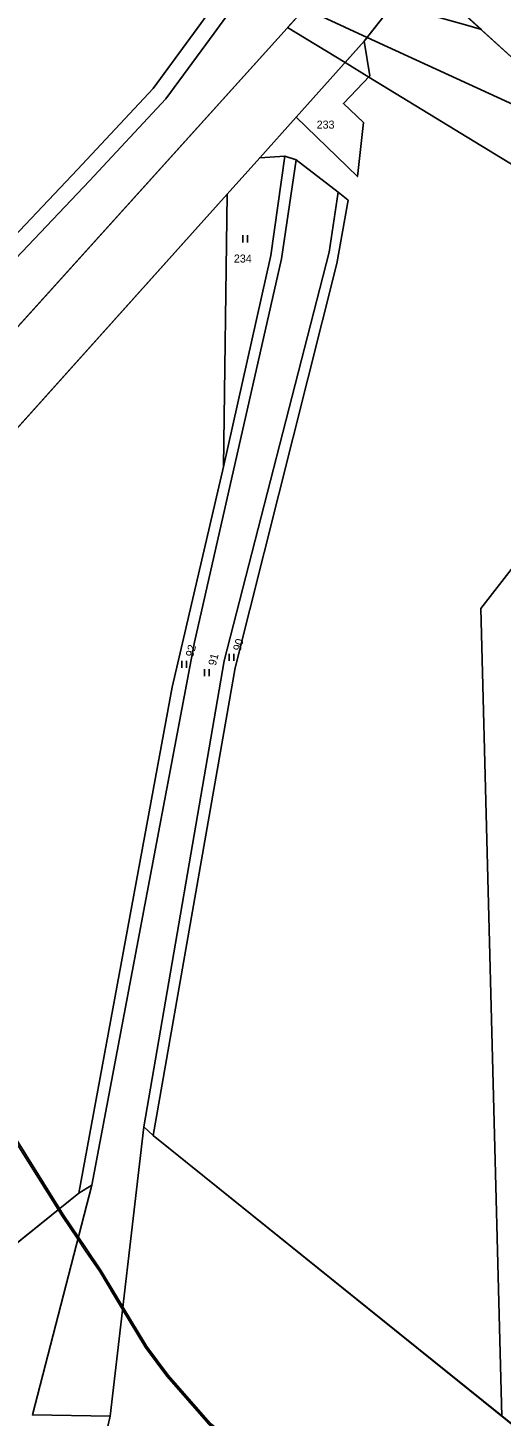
# Model space of a CAD drawing. Extents: x -689422 to -685210, y -987725 to -982160.
# Drawn here: x -685954.8 to -685854.1, y -987007.8 to -986712.9 of the extents above; entities that cross this region are included whole.
import ezdxf

# ---------------------------------------------------------------- set-up
doc = ezdxf.new("R2010")
doc.units = 0
for name, color, linetype in [('KN_Hranice_parcel', 7, 'Continuous'), ('KN_Parcelni cisla', 7, 'Continuous'), ('KN_Polygon parcely', 7, 'Continuous'), ('KN_POZEMKY_ORNA PUDA', 7, 'Continuous'), ('KN_POZEMKY_OSTATNI PLOCHA', 7, 'Continuous'), ('KN_POZEMKY_TTP', 7, 'Continuous'), ('KN_VYUZITI_16_ostatni plocha_silnice', 7, 'Continuous'), ('KN_VYUZITI_17_ostatni plocha_ostatni komunikace', 7, 'Continuous'), ('KN_VYUZITI_23_ostatni plocha_manipulacni plocha', 7, 'Continuous'), ('KN_Věcná břemena k části', 7, 'Continuous'), ('KN_Značky kultur', 7, 'Continuous')]:
    doc.layers.add(name, color=color, linetype=linetype)

msp = doc.modelspace()

# ---------------------------------------------------------------- linework, layer by layer
at = {"layer": 'KN_Hranice_parcel'}
for p, q in [((-685871.78, -986701.06), (-685883.26, -986715.76)), ((-685848.24, -986722.49), (-685871.78, -986701.06)), ((-685896.42, -986709.33), (-686030, -986857.27)), ((-685897.76, -986731.9), (-685883.26, -986715.76)), ((-685897.76, -986731.9), (-685905.48, -986740.5)), ((-685905.48, -986740.5), (-685900.17, -986740.16)), ((-685900.17, -986740.16), (-685897.77, -986740.94)), ((-685912.44, -986748.24), (-685905.48, -986740.5)), ((-685897.77, -986740.94), (-685888.84, -986747.84)), ((-685912.44, -986748.24), (-686007.7, -986854.28)), ((-685913.21, -986806.14), (-685912.44, -986748.24)), ((-685930.15, -986946.38), (-685937.3, -987007.82)), ((-685928.15, -986948.17), (-685930.15, -986946.38)), ((-685841.86, -987017.57), (-685928.15, -986948.17)), ((-685943.98, -986960.44), (-686030.41, -987030.08)), ((-685953.84, -987007.56), (-685941.2, -986958.77)), ((-685941.2, -986958.77), (-685943.98, -986960.44)), ((-685937.3, -987007.82), (-685953.84, -987007.56))]:
    msp.add_line(p, q, dxfattribs=at)
for points in [[(-685883.26, -986715.76), (-685882.04, -986723.11), (-685887.69, -986728.97), (-685883.44, -986733.01), (-685884.73, -986744.52), (-685897.76, -986731.9)], [(-685900.17, -986740.16), (-685903.1, -986761.27), (-685913.21, -986806.14)], [(-685897.77, -986740.94), (-685900.89, -986761.99), (-685919.33, -986843.38), (-685941.2, -986958.77)], [(-685888.84, -986747.84), (-685890.73, -986760.55), (-685913.08, -986847.4), (-685930.15, -986946.38)], [(-685888.84, -986747.84), (-685886.69, -986749.54), (-685889.1, -986762.96), (-685910.74, -986848.85), (-685928.15, -986948.17)], [(-685943.98, -986960.44), (-685924.13, -986852.94), (-685913.21, -986806.14)], [(-685937.3, -987007.82), (-685938.29, -987012.04), (-685944.18, -987021.29), (-685944.36, -987022.19)]]:
    msp.add_lwpolyline(points, dxfattribs=at)
at = {"layer": 'KN_Polygon parcely'}
for points in [[(-686030, -986857.27), (-685896.42, -986709.33), (-685879.25, -986604.88), (-685888.64, -986596.36), (-685893.37, -986592.13), (-685934.98, -986554.78), (-685848.74, -986459.34), (-685824.6, -986333.83), (-685808.02, -986261.49), (-685804.53, -986262.81), (-685805.53, -986255.07), (-685812.11, -986245.12), (-685839.77, -986231.67)], [(-686007.7, -986854.28), (-685912.44, -986748.24), (-685905.48, -986740.5), (-685897.76, -986731.9), (-685883.26, -986715.76), (-685871.78, -986701.06), (-685873.39, -986699.91), (-685878.76, -986694.71), (-685879.32, -986694.17), (-685881.14, -986692.41), (-685892.53, -986705.03), (-685896.42, -986709.33), (-686030, -986857.27)], [(-685871.78, -986701.06), (-685848.24, -986722.49), (-685839.62, -986712.96), (-685835.01, -986707.92)], [(-685841.86, -987017.57), (-685928.15, -986948.17), (-685930.15, -986946.38), (-685937.3, -987007.82), (-685938.29, -987012.04)]]:
    msp.add_lwpolyline(points, dxfattribs=at)
for points in [[(-685848.24, -986722.49), (-685871.78, -986701.06), (-685883.26, -986715.76), (-685882.04, -986723.11), (-685887.69, -986728.97), (-685883.44, -986733.01), (-685884.73, -986744.52), (-685897.76, -986731.9), (-685905.48, -986740.5), (-685900.17, -986740.16), (-685897.77, -986740.94), (-685888.84, -986747.84), (-685886.69, -986749.54), (-685889.1, -986762.96), (-685910.74, -986848.85), (-685928.15, -986948.17), (-685841.86, -987017.57), (-685785.3, -986953.97), (-685700.06, -986858.13), (-685729.36, -986831.55), (-685790.39, -986775.56)], [(-685883.26, -986715.76), (-685897.76, -986731.9), (-685884.73, -986744.52), (-685883.44, -986733.01), (-685887.69, -986728.97), (-685882.04, -986723.11)], [(-685913.21, -986806.14), (-685924.13, -986852.94), (-685943.98, -986960.44), (-685941.2, -986958.77), (-685919.33, -986843.38), (-685900.89, -986761.99), (-685897.77, -986740.94), (-685900.17, -986740.16), (-685903.1, -986761.27)], [(-685900.17, -986740.16), (-685905.48, -986740.5), (-685912.44, -986748.24), (-685913.21, -986806.14), (-685903.1, -986761.27)], [(-685919.33, -986843.38), (-685941.2, -986958.77), (-685953.84, -987007.56), (-685937.3, -987007.82), (-685930.15, -986946.38), (-685913.08, -986847.4), (-685890.73, -986760.55), (-685888.84, -986747.84), (-685897.77, -986740.94), (-685900.89, -986761.99)], [(-686057.95, -987027.77), (-686044.81, -987042.84), (-686030.41, -987030.08), (-685943.98, -986960.44), (-685924.13, -986852.94), (-685913.21, -986806.14), (-685912.44, -986748.24), (-686007.7, -986854.28), (-685997.69, -986881.99), (-685975.19, -986944.25), (-685978.21, -986945.31), (-686044.53, -986968.62), (-686066.56, -986976.83), (-686064.65, -986989.12), (-686058.05, -987027.25)], [(-685890.73, -986760.55), (-685913.08, -986847.4), (-685930.15, -986946.38), (-685928.15, -986948.17), (-685910.74, -986848.85), (-685889.1, -986762.96), (-685886.69, -986749.54), (-685888.84, -986747.84)], [(-686016.2, -987083.11), (-686028.95, -987043.29), (-685988.6, -987031.04), (-685980.6, -987028.61), (-685982.92, -987021.97), (-685962.77, -987015.13), (-685959.63, -987023.64), (-685951.53, -987020.94), (-685949.91, -987021.19), (-685944.36, -987022.19), (-685944.18, -987021.29), (-685938.29, -987012.04), (-685937.3, -987007.82), (-685953.84, -987007.56), (-685941.2, -986958.77), (-685943.98, -986960.44), (-686030.41, -987030.08), (-686044.81, -987042.84), (-686051.22, -987045.66), (-686050.62, -987047.03), (-686049.49, -987051.75), (-686046.44, -987058.66), (-686042.51, -987067.97), (-686047.8, -987093.66)]]:
    msp.add_lwpolyline(points, close=True, dxfattribs=at)
at = {"layer": 'KN_POZEMKY_ORNA PUDA'}
for p, q in [((-685883.26, -986715.76), (-685871.78, -986701.06)), ((-685871.78, -986701.06), (-685848.24, -986722.49)), ((-685896.42, -986709.33), (-686030, -986857.27)), ((-685882.04, -986723.11), (-685883.26, -986715.76)), ((-685887.69, -986728.97), (-685882.04, -986723.11)), ((-685883.44, -986733.01), (-685887.69, -986728.97)), ((-685905.48, -986740.5), (-685897.76, -986731.9)), ((-685897.76, -986731.9), (-685884.73, -986744.52)), ((-685884.73, -986744.52), (-685883.44, -986733.01)), ((-685900.17, -986740.16), (-685905.48, -986740.5)), ((-685897.77, -986740.94), (-685900.17, -986740.16)), ((-685888.84, -986747.84), (-685897.77, -986740.94)), ((-686007.7, -986854.28), (-685912.44, -986748.24)), ((-685912.44, -986748.24), (-685913.21, -986806.14)), ((-685886.69, -986749.54), (-685888.84, -986747.84)), ((-685889.1, -986762.96), (-685886.69, -986749.54)), ((-685910.74, -986848.85), (-685889.1, -986762.96)), ((-685913.21, -986806.14), (-685924.13, -986852.94)), ((-685928.15, -986948.17), (-685910.74, -986848.85)), ((-685924.13, -986852.94), (-685943.98, -986960.44)), ((-685841.86, -987017.57), (-685928.15, -986948.17)), ((-685943.98, -986960.44), (-686030.41, -987030.08))]:
    msp.add_line(p, q, dxfattribs=at)
at = {"layer": 'KN_POZEMKY_OSTATNI PLOCHA'}
for p, q in [((-685871.78, -986701.06), (-685883.26, -986715.76)), ((-685848.24, -986722.49), (-685871.78, -986701.06)), ((-686030, -986857.27), (-685896.42, -986709.33)), ((-685883.26, -986715.76), (-685897.76, -986731.9)), ((-685897.76, -986731.9), (-685883.26, -986715.76)), ((-685883.26, -986715.76), (-685882.04, -986723.11)), ((-685882.04, -986723.11), (-685887.69, -986728.97)), ((-685887.69, -986728.97), (-685883.44, -986733.01)), ((-685897.76, -986731.9), (-685905.48, -986740.5)), ((-685884.73, -986744.52), (-685897.76, -986731.9)), ((-685883.44, -986733.01), (-685884.73, -986744.52)), ((-685905.48, -986740.5), (-685912.44, -986748.24)), ((-685912.44, -986748.24), (-686007.7, -986854.28)), ((-686030.41, -987030.08), (-685943.98, -986960.44)), ((-685941.2, -986958.77), (-685953.84, -987007.56)), ((-685943.98, -986960.44), (-685941.2, -986958.77)), ((-685953.84, -987007.56), (-685937.3, -987007.82)), ((-685937.3, -987007.82), (-685938.29, -987012.04))]:
    msp.add_line(p, q, dxfattribs=at)
at = {"layer": 'KN_POZEMKY_TTP'}
for p, q in [((-685905.48, -986740.5), (-685900.17, -986740.16)), ((-685900.17, -986740.16), (-685903.1, -986761.27)), ((-685903.1, -986761.27), (-685900.17, -986740.16)), ((-685900.17, -986740.16), (-685897.77, -986740.94)), ((-685912.44, -986748.24), (-685905.48, -986740.5)), ((-685900.89, -986761.99), (-685897.77, -986740.94)), ((-685897.77, -986740.94), (-685900.89, -986761.99)), ((-685897.77, -986740.94), (-685888.84, -986747.84)), ((-685913.21, -986806.14), (-685912.44, -986748.24)), ((-685888.84, -986747.84), (-685890.73, -986760.55)), ((-685890.73, -986760.55), (-685888.84, -986747.84)), ((-685888.84, -986747.84), (-685886.69, -986749.54)), ((-685886.69, -986749.54), (-685889.1, -986762.96)), ((-685890.73, -986760.55), (-685913.08, -986847.4)), ((-685913.08, -986847.4), (-685890.73, -986760.55)), ((-685919.33, -986843.38), (-685900.89, -986761.99)), ((-685900.89, -986761.99), (-685919.33, -986843.38)), ((-685903.1, -986761.27), (-685913.21, -986806.14)), ((-685913.21, -986806.14), (-685903.1, -986761.27)), ((-685889.1, -986762.96), (-685910.74, -986848.85)), ((-685924.13, -986852.94), (-685913.21, -986806.14)), ((-685941.2, -986958.77), (-685919.33, -986843.38)), ((-685919.33, -986843.38), (-685941.2, -986958.77)), ((-685913.08, -986847.4), (-685930.15, -986946.38)), ((-685930.15, -986946.38), (-685913.08, -986847.4)), ((-685910.74, -986848.85), (-685928.15, -986948.17)), ((-685943.98, -986960.44), (-685924.13, -986852.94)), ((-685937.3, -987007.82), (-685930.15, -986946.38)), ((-685930.15, -986946.38), (-685937.3, -987007.82)), ((-685930.15, -986946.38), (-685928.15, -986948.17)), ((-685928.15, -986948.17), (-685930.15, -986946.38)), ((-685928.15, -986948.17), (-685841.86, -987017.57)), ((-685953.84, -987007.56), (-685941.2, -986958.77)), ((-685941.2, -986958.77), (-685943.98, -986960.44)), ((-685937.3, -987007.82), (-685953.84, -987007.56)), ((-685938.29, -987012.04), (-685937.3, -987007.82))]:
    msp.add_line(p, q, dxfattribs=at)
at = {"layer": 'KN_VYUZITI_16_ostatni plocha_silnice'}
for p, q in [((-685871.78, -986701.06), (-685883.26, -986715.76)), ((-686030, -986857.27), (-685896.42, -986709.33)), ((-685883.26, -986715.76), (-685897.76, -986731.9)), ((-685897.76, -986731.9), (-685905.48, -986740.5)), ((-685905.48, -986740.5), (-685912.44, -986748.24)), ((-685912.44, -986748.24), (-686007.7, -986854.28))]:
    msp.add_line(p, q, dxfattribs=at)
at = {"layer": 'KN_VYUZITI_17_ostatni plocha_ostatni komunikace'}
for p, q in [((-685897.76, -986731.9), (-685883.26, -986715.76)), ((-685883.26, -986715.76), (-685882.04, -986723.11)), ((-685882.04, -986723.11), (-685887.69, -986728.97)), ((-685887.69, -986728.97), (-685883.44, -986733.01)), ((-685884.73, -986744.52), (-685897.76, -986731.9)), ((-685883.44, -986733.01), (-685884.73, -986744.52))]:
    msp.add_line(p, q, dxfattribs=at)
at = {"layer": 'KN_VYUZITI_23_ostatni plocha_manipulacni plocha'}
for p, q in [((-685848.24, -986722.49), (-685871.78, -986701.06)), ((-686030.41, -987030.08), (-685943.98, -986960.44)), ((-685941.2, -986958.77), (-685953.84, -987007.56)), ((-685943.98, -986960.44), (-685941.2, -986958.77)), ((-685953.84, -987007.56), (-685937.3, -987007.82)), ((-685937.3, -987007.82), (-685938.29, -987012.04))]:
    msp.add_line(p, q, dxfattribs=at)
at = {"layer": 'KN_Věcná břemena k části'}
for points in [[(-686029.97, -986842.1), (-686030.24, -986841.61), (-686018.66, -986828.44), (-686002.29, -986809.43), (-685978.75, -986785.37), (-685963.92, -986768.8), (-685941.71, -986745.38), (-685925.43, -986728.01), (-685915.2, -986714.04), (-685896.7, -986688.59), (-685890.74, -986683.93), (-685888.88, -986684.19), (-685888.29, -986680.83), (-685891.79, -986680.82), (-685899.18, -986686.06), (-685918.03, -986711.98), (-685928.12, -986725.77), (-685944.25, -986742.97), (-685966.52, -986766.47), (-685981.25, -986782.92), (-686004.94, -986807.14), (-686021.29, -986826.13), (-686034.48, -986841.14), (-686033.05, -986843.77)], [(-685875.49, -986705.81), (-685877.53, -986708.43), (-685866.85, -986710.82), (-685861.73, -986712.29), (-685858.35, -986713.29), (-685863.4, -986708.69), (-685866.11, -986707.92)], [(-685895.97, -986708.83), (-685896.42, -986709.33), (-685899.57, -986712.82), (-685887.33, -986720.29), (-685883.26, -986715.76), (-685882.62, -986714.95)], [(-685882.62, -986714.95), (-685883.26, -986715.76), (-685887.33, -986720.29), (-685882.28, -986723.36), (-685837.22, -986750.85), (-685824.97, -986743.84), (-685835.82, -986733.88), (-685837.66, -986735.55)], [(-685802.51, -986764.44), (-685858.43, -986836.26), (-685854.41, -986991.75), (-685853.98, -987007.82), (-685841.86, -987017.57), (-685835.4, -987010.31), (-685825.2, -986845.79), (-685775.19, -986789.51), (-685790.39, -986775.56)], [(-686001.37, -986863.76), (-685996.91, -986874), (-685988.75, -986891.62), (-685973.95, -986920.83), (-685958.96, -986947), (-685948.34, -986963.95), (-685948.05, -986963.72), (-685958.66, -986946.82), (-685973.65, -986920.67), (-685988.43, -986891.46), (-685996.59, -986873.86), (-686001.05, -986863.64), (-686003.74, -986854.88), (-686006.31, -986852.73), (-686006.54, -986852.99), (-686004.04, -986855.08)], [(-685944.17, -986970.22), (-685944.05, -986969.77), (-685947.26, -986964.99), (-685948.05, -986963.72), (-685948.34, -986963.95), (-685947.56, -986965.19)], [(-685934.66, -986985.17), (-685934.6, -986984.59), (-685936.28, -986981.8), (-685939.21, -986976.95), (-685942.41, -986972.21), (-685944.05, -986969.77), (-685944.17, -986970.22), (-685942.51, -986972.68), (-685939.51, -986977.13), (-685936.39, -986982.31)], [(-685934.6, -986984.59), (-685934.66, -986985.17), (-685929.79, -986993.25), (-685925.24, -986999.35), (-685916.25, -987009.6), (-685903.69, -987019.71), (-685891.14, -987029.18), (-685886.44, -987031.68), (-685877, -987034.5), (-685854.55, -987038.35), (-685854.26, -987038.04), (-685854.44, -987038.01), (-685876.92, -987034.16), (-685886.3, -987031.36), (-685890.96, -987028.88), (-685903.47, -987019.43), (-685916.01, -987009.34), (-685924.96, -986999.13), (-685929.49, -986993.05)]]:
    msp.add_lwpolyline(points, close=True, dxfattribs=at)
at = {"layer": 'KN_Značky kultur'}
for p, q in [((-685909.08, -986758.48), (-685909.08, -986756.98)), ((-685908.08, -986758.48), (-685908.08, -986756.98)), ((-685911.99, -986847.36), (-685911.99, -986845.86)), ((-685910.99, -986847.36), (-685910.99, -986845.86)), ((-685922.08, -986848.89), (-685922.08, -986847.39)), ((-685921.08, -986848.89), (-685921.08, -986847.39)), ((-685917.22, -986850.62), (-685917.22, -986849.12)), ((-685916.22, -986850.62), (-685916.22, -986849.12))]:
    msp.add_line(p, q, dxfattribs=at)

# ---------------------------------------------------------------- texts
at = {"layer": 'KN_Parcelni cisla'}
for s, p in [('233', (-685893.38, -986734.31)), ('234', (-685910.98, -986762.76))]:
    msp.add_text(s, height=1.7, dxfattribs=at).set_placement(p)
for s, rotation, p in [('90', 74, (-685909.58, -986845.4)), ('92', 75, (-685919.65, -986846.65)), ('91', 76, (-685914.83, -986848.51))]:
    msp.add_text(s, height=1.7, rotation=rotation, dxfattribs=at).set_placement(p)

doc.saveas('drawing.dxf')
